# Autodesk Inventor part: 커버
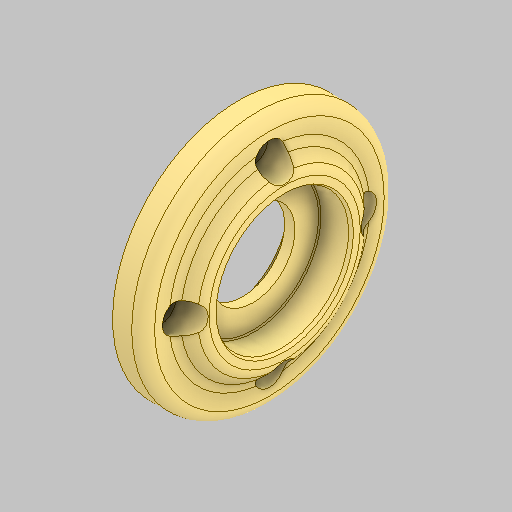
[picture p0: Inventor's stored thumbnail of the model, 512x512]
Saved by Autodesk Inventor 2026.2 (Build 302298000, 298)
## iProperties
Created: 2026-06
Part Number: 커버
Material: 알루미늄 6061
Document SubType Name: Modeling
Designer: sec7
Density: 2.7 g/cm^3
Appearance: 기본값
Author: jhkim
Sending System: Autodesk Inventor 2027
Preprocessor: ST-DEVELOPER v20.1
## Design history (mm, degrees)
feature "솔리드1"
node "솔리드2"
